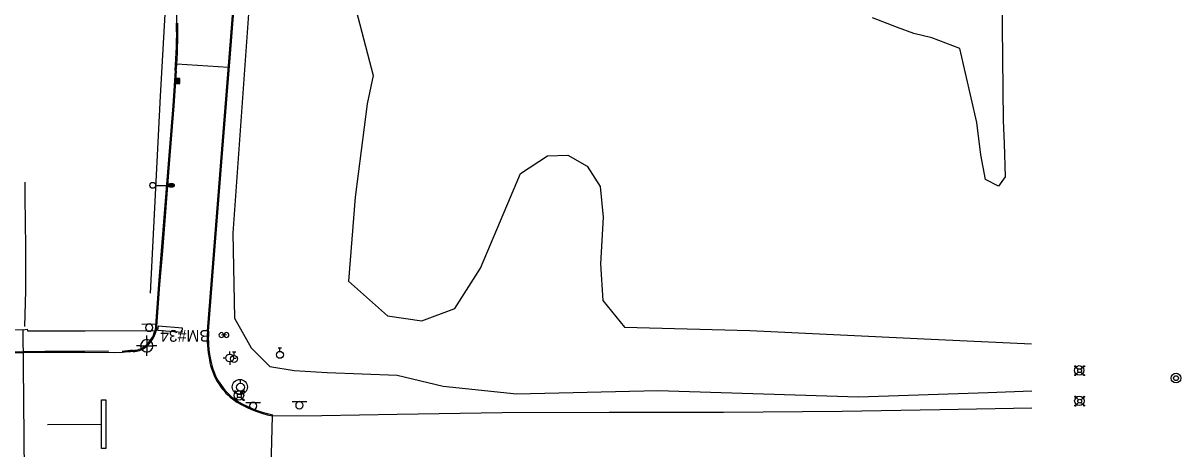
# Model space of a CAD drawing. Extents: x 2145380 to 2156929, y 139568 to 149130.
# Drawn here: x 2150933 to 2151525, y 140326 to 140544 of the extents above; entities that cross this region are included whole.
import ezdxf

# ---------------------------------------------------------------- set-up
doc = ezdxf.new("R2010")
doc.units = 0
for name, color, linetype in [('Default', 7, 'Continuous'), ('SURV_Benchmark', 7, 'Continuous'), ('SURV_Text', 7, 'Continuous'), ('TOPO_Asphalt', 7, 'Continuous'), ('TOPO_BRIDGE_Floor Deck', 7, 'Continuous'), ('TOPO_Curb Back', 7, 'Continuous'), ('TOPO_Fence', 7, 'Continuous'), ('TOPO_Flowline', 7, 'Continuous'), ('TOPO_Light Pole', 7, 'Continuous'), ('TOPO_Misc', 7, 'Continuous'), ('TOPO_Misc Line', 7, 'Continuous'), ('TOPO_Power Pole', 7, 'Continuous'), ('TOPO_San Manhole', 7, 'Continuous'), ('TOPO_Sidewalk', 7, 'Continuous'), ('TOPO_Sign', 7, 'Continuous'), ('TOPO_Tree', 7, 'Continuous'), ('TOPO_Wall Freestanding', 7, 'Continuous'), ('TOPO_Water Fire Hydrant', 7, 'Continuous'), ('TOPO_Water Valve', 7, 'Continuous')]:
    doc.layers.add(name, color=color, linetype=linetype)

# ---------------------------------------------------------------- blocks, each defined once
blk = doc.blocks.new('POST')
at = {"layer": 'TOPO_Misc'}
for start, end in [(90, 180), (180, 270), (360, 90), (270, 0)]:
    blk.add_arc((0, 0), 3.16, start, end, dxfattribs=at)
blk = doc.blocks.new('FIRHYD')
at = {"layer": 'TOPO_Water Fire Hydrant'}
for p, q in [((0, 10.2), (0, 17.3)), ((10.2, 0), (17.3, 0)), ((-10.2, 0), (-17.3, 0)), ((0, -10.2), (0, -17.3))]:
    blk.add_line(p, q, dxfattribs=at)
blk.add_circle((0, 0), 10.2, dxfattribs=at)
blk = doc.blocks.new('LP')
at = {"layer": 'TOPO_Light Pole'}
blk.add_line((3.8, 0), (20.3, 0), dxfattribs=at)
for points in [[(20.3, 0), (27.9, 0)], [(20.3, 0), (23.5, 0)], [(20.8, 1.3), (27.4, 1.3)], [(20.8, 1.3), (23.5, 1.3)], [(23.7, 1.3), (27.4, 1.3)], [(23.7, 0), (27.9, 0)], [(20.8, -1.3), (27.4, -1.3)], [(20.8, -1.3), (23.5, -1.3)], [(23.7, -1.3), (27.4, -1.3)]]:
    blk.add_lwpolyline(points, dxfattribs=at)
blk.add_circle((0, 0), 3.81, dxfattribs=at)
blk.add_ellipse((24.1, 0), major_axis=(3.81, 0), ratio=0.666667, dxfattribs=at)
blk = doc.blocks.new('CB')
at = {"layer": 'TOPO_Misc'}
for p, q in [((-3.1, 3), (3.2, 3)), ((-3.1, 2.7), (3.2, 2.7)), ((-3.1, 2.4), (3.2, 2.4)), ((-3.1, 2), (3.2, 2)), ((-3.1, 1.7), (3.2, 1.7)), ((-3.1, 1.4), (3.2, 1.4)), ((-3.1, 1.1), (3.2, 1.1)), ((-3.1, 0.8), (3.2, 0.8)), ((-3.1, 0.5), (3.2, 0.5)), ((-3.1, 0.1), (3.2, 0.1)), ((-3.1, -0.2), (3.2, -0.2)), ((-3.1, -0.5), (3.2, -0.5)), ((-3.1, -0.8), (3.2, -0.8)), ((-3.1, -1.1), (3.3, -1.1)), ((-3.1, -1.4), (3.3, -1.4)), ((-3.1, -1.8), (3.3, -1.8)), ((-3.1, -2.1), (3.3, -2.1)), ((-3.1, -2.4), (3.3, -2.4)), ((-3.1, -2.7), (3.3, -2.7)), ((-3.1, -3), (3.3, -3))]:
    blk.add_line(p, q, dxfattribs=at)
blk.add_lwpolyline([(3.3, -3.3), (3.2, 3.1), (-3.1, 3), (-3.1, -3.3), (3.3, -3.3)], dxfattribs=at)
blk = doc.blocks.new('POWPOL')
at = {"layer": 'TOPO_Power Pole'}
for p, q in [((0, 10.2), (0, 17.3)), ((0, -10.2), (0, -17.3))]:
    blk.add_line(p, q, dxfattribs=at)
blk.add_circle((0, 0), 10.2, dxfattribs=at)
blk = doc.blocks.new('HIGHMAST')
at = {"layer": 'Default'}
for p, q in [((-6.4, 5.7), (-6.2, 6.2)), ((-6.2, 5.2), (-6.4, 5.7)), ((-6.3, 5.9), (-5.9, 6.3)), ((-6.2, 5.3), (-6.3, 5.9)), ((-6.3, 5.7), (-5.2, 5.6)), ((-5.6, 5.1), (-6.3, 5.7)), ((-6.2, 6.2), (-5.7, 6.4)), ((-6.2, 5.8), (-5.9, 6.2)), ((-6.1, 5.4), (-6.2, 5.8)), ((-6.2, 5.3), (-6.2, 5.3)), ((-5.7, 5.1), (-6.2, 5.3)), ((-6.2, 5.2), (-6.2, 5.2)), ((-5.7, 5), (-6.2, 5.2)), ((-6.1, 5.7), (-5.8, 6)), ((-5.7, 5.4), (-6.1, 5.7)), ((-6.1, 5.4), (-6.1, 5.4)), ((-5.6, 5.2), (-6.1, 5.4)), ((-6, 5.9), (-5.5, 6)), ((-6, 5.5), (-6, 5.9)), ((-6, 5.5), (-6, 5.5)), ((-5.5, 5.4), (-6, 5.5)), ((-5.9, 6.3), (-5.3, 6.1)), ((-5.9, 6.2), (-5.4, 6.1)), ((-5.8, 5.8), (-5.9, 5.7)), ((-5.9, 5.7), (-5.8, 5.5)), ((-5.8, 6.3), (-5.6, 5.1)), ((-5.8, 5.8), (-5.8, 6.3)), ((-5.8, 6), (-5.8, 5.8)), ((-5.8, 6), (-5.4, 5.6)), ((-5.6, 5.6), (-5.8, 5.8)), ((-5.8, 5.5), (-5.6, 5.6)), ((-5.7, 6.4), (-5.2, 6.2)), ((-5.4, 5.6), (-5.7, 5.4)), ((-5.3, 5.3), (-5.7, 5.1)), ((-5.2, 5.2), (-5.7, 5)), ((-5.3, 5.6), (-5.6, 5.2)), ((-5.5, 6), (-5.5, 6)), ((-5.5, 6), (-5.5, 5.4)), ((-5.4, 6.1), (-5.4, 6)), ((-5.4, 6), (-5.3, 5.6)), ((-5.3, 6.1), (-5.3, 6.1)), ((-5.3, 6.1), (-5.1, 5.7)), ((-5.1, 5.7), (-5.3, 5.3)), ((-5.2, 6.2), (-5, 5.7)), ((-5.2, 6.2), (-5.2, 6.2)), ((-5, 5.7), (-5.2, 5.2)), ((-5.2, 5.2), (-1.8, 1.8)), ((5.2, 5.2), (1.8, 1.8)), ((5, 5.7), (5.2, 6.2)), ((5.2, 5.2), (5, 5.7)), ((5.1, 5.6), (5.7, 6.3)), ((5.1, 5.7), (5.3, 6.2)), ((6.3, 5.8), (5.1, 5.6)), ((5.3, 5.3), (5.1, 5.7)), ((5.2, 6.2), (5.7, 6.4)), ((5.2, 6.2), (5.2, 6.2)), ((5.2, 5.6), (5.4, 6.1)), ((5.6, 5.3), (5.2, 5.6)), ((5.7, 5), (5.2, 5.2)), ((5.3, 6.2), (5.9, 6.3)), ((5.3, 6.2), (5.3, 6.2)), ((5.7, 5.1), (5.3, 5.3)), ((5.4, 6.1), (5.8, 6.2)), ((5.4, 5.7), (5.7, 6.1)), ((5.4, 6.1), (5.4, 6.1)), ((5.4, 5.5), (5.5, 6)), ((5.6, 5.4), (5.4, 5.7)), ((6, 5.5), (5.4, 5.5)), ((5.5, 6), (5.9, 6)), ((5.5, 6), (5.5, 6)), ((5.7, 5.9), (5.5, 5.8)), ((5.5, 5.8), (5.6, 5.6)), ((5.7, 6.3), (5.6, 5.2)), ((5.6, 5.6), (5.8, 5.8)), ((6, 5.8), (5.6, 5.4)), ((6, 5.4), (5.6, 5.3)), ((5.7, 6.4), (6.2, 6.2)), ((5.7, 6.1), (6, 5.8)), ((5.8, 5.8), (5.7, 5.9)), ((6.1, 5.3), (5.7, 5.1)), ((6.2, 5.2), (5.7, 5)), ((5.8, 6.2), (6.2, 5.9)), ((5.8, 5.8), (6.3, 5.8)), ((6, 5.8), (5.8, 5.8)), ((5.9, 6.3), (6.3, 5.9)), ((5.9, 6), (6, 5.5)), ((6, 5.5), (6, 5.5)), ((6.1, 5.4), (6, 5.4)), ((6.2, 5.9), (6.1, 5.4)), ((6.3, 5.9), (6.1, 5.3)), ((6.1, 5.3), (6.1, 5.3)), ((6.2, 6.2), (6.4, 5.7)), ((6.4, 5.7), (6.2, 5.2)), ((6.2, 5.2), (6.2, 5.2)), ((-6.4, -5.7), (-6.2, -5.2)), ((-6.2, -6.2), (-6.4, -5.7)), ((-6.3, -5.9), (-6.1, -5.3)), ((-6.3, -5.8), (-5.1, -5.6)), ((-5.8, -5.8), (-6.3, -5.8)), ((-5.9, -6.3), (-6.3, -5.9)), ((-6.2, -5.2), (-5.7, -5)), ((-6.2, -5.2), (-6.2, -5.2)), ((-6.2, -5.9), (-6.1, -5.4)), ((-5.8, -6.2), (-6.2, -5.9)), ((-5.7, -6.4), (-6.2, -6.2)), ((-6.1, -5.3), (-5.7, -5.1)), ((-6.1, -5.3), (-6.1, -5.3)), ((-6.1, -5.4), (-6, -5.4)), ((-6, -5.4), (-5.6, -5.3)), ((-6, -5.8), (-5.6, -5.4)), ((-6, -5.5), (-6, -5.5)), ((-5.9, -6), (-6, -5.5)), ((-6, -5.5), (-5.4, -5.5)), ((-6, -5.8), (-5.8, -5.8)), ((-5.7, -6.1), (-6, -5.8)), ((-5.5, -6), (-5.9, -6)), ((-5.3, -6.2), (-5.9, -6.3)), ((-5.6, -5.6), (-5.8, -5.8)), ((-5.8, -5.8), (-5.7, -5.9)), ((-5.4, -6.1), (-5.8, -6.2)), ((-5.7, -5), (-5.2, -5.2)), ((-5.7, -5.1), (-5.3, -5.3)), ((-5.7, -6.3), (-5.6, -5.2)), ((-5.1, -5.6), (-5.7, -6.3)), ((-5.4, -5.7), (-5.7, -6.1)), ((-5.7, -5.9), (-5.5, -5.8)), ((-5.2, -6.2), (-5.7, -6.4)), ((-5.6, -5.3), (-5.2, -5.6)), ((-5.6, -5.4), (-5.4, -5.7)), ((-5.5, -5.8), (-5.6, -5.6)), ((-5.4, -5.5), (-5.5, -6)), ((-5.5, -6), (-5.5, -6)), ((-5.2, -5.6), (-5.4, -6.1)), ((-5.4, -6.1), (-5.4, -6.1)), ((-5.3, -5.3), (-5.1, -5.7)), ((-5.1, -5.7), (-5.3, -6.2)), ((-5.3, -6.2), (-5.3, -6.2)), ((-5.2, -5.2), (-1.8, -1.8)), ((-5.2, -5.2), (-5, -5.7)), ((-5, -5.7), (-5.2, -6.2)), ((-5.2, -6.2), (-5.2, -6.2)), ((5.2, -5.2), (1.8, -1.8)), ((5, -5.7), (5.2, -5.2)), ((5.2, -6.2), (5, -5.7)), ((5.1, -5.7), (5.3, -5.3)), ((5.3, -6.1), (5.1, -5.7)), ((5.2, -5.2), (5.7, -5)), ((6.3, -5.7), (5.2, -5.6)), ((5.7, -6.4), (5.2, -6.2)), ((5.2, -6.2), (5.2, -6.2)), ((5.3, -5.3), (5.7, -5.1)), ((5.3, -5.6), (5.6, -5.2)), ((5.4, -6), (5.3, -5.6)), ((5.3, -6.1), (5.3, -6.1)), ((5.9, -6.3), (5.3, -6.1)), ((5.4, -5.6), (5.7, -5.4)), ((5.8, -6), (5.4, -5.6)), ((5.4, -6.1), (5.4, -6)), ((5.9, -6.2), (5.4, -6.1)), ((5.5, -5.4), (6, -5.5)), ((5.5, -6), (5.5, -5.4)), ((6, -5.9), (5.5, -6)), ((5.5, -6), (5.5, -6)), ((5.6, -5.1), (6.3, -5.7)), ((5.8, -6.3), (5.6, -5.1)), ((5.6, -5.2), (6.1, -5.4)), ((5.8, -5.5), (5.6, -5.6)), ((5.6, -5.6), (5.8, -5.8)), ((5.7, -5), (6.2, -5.2)), ((5.7, -5.1), (6.2, -5.3)), ((5.7, -5.4), (6.1, -5.7)), ((6.2, -6.2), (5.7, -6.4)), ((5.9, -5.7), (5.8, -5.5)), ((5.8, -5.8), (5.9, -5.7)), ((6.1, -5.7), (5.8, -6)), ((5.8, -5.8), (5.8, -6.3)), ((5.8, -6), (5.8, -5.8)), ((6.2, -5.8), (5.9, -6.2)), ((6.3, -5.9), (5.9, -6.3)), ((6, -5.5), (6, -5.9)), ((6, -5.5), (6, -5.5)), ((6.1, -5.4), (6.2, -5.8)), ((6.1, -5.4), (6.1, -5.4)), ((6.2, -5.2), (6.2, -5.2)), ((6.2, -5.2), (6.4, -5.7)), ((6.2, -5.3), (6.3, -5.9)), ((6.2, -5.3), (6.2, -5.3)), ((6.4, -5.7), (6.2, -6.2))]:
    blk.add_line(p, q, dxfattribs=at)
for centre, radius in [((-0.5, 0.4), 6.15), ((0, 0), 2.5), ((0, 0), 2.5), ((0, 0), 2.5), ((0, 0), 2.5)]:
    blk.add_circle(centre, radius, dxfattribs=at)
blk = doc.blocks.new('WATVAL')
at = {"layer": 'Default'}
for p, q in [((-2.2, 9), (2.2, 9)), ((0, 4.5), (0, 9))]:
    blk.add_line(p, q, dxfattribs=at)
blk.add_circle((0, 0), 4.5, dxfattribs=at)
blk = doc.blocks.new('EXMHSS')
at = {"layer": 'Default'}
for radius in [6.3, 3.13]:
    blk.add_circle((0, 0), radius, dxfattribs=at)
blk = doc.blocks.new('BM')
at = {"layer": 'SURV_Benchmark'}
for p, q in [((-2.49, 0), (-4.16, 0)), ((0, 2.49), (0, 4.15)), ((4.16, 0), (2.49, 0)), ((0, -4.16), (0, -2.49))]:
    blk.add_line(p, q, dxfattribs=at)
for points in [[(-2.5, 0), (-2.49, 0), (0, 0), (0, -2.49), (0, -2.49)], [(-2.5, 0), (-2.49, 0), (0, 0), (0, -2.49), (0, -2.49)], [(0, 2.49), (0, 2.49), (0, 0), (2.49, 0), (2.49, 0), (2.49, 0)], [(0, 2.49), (0, 2.49), (0, 0), (2.49, 0), (2.49, 0), (2.49, 0), (2.49, 0)]]:
    blk.add_lwpolyline(points, dxfattribs=at)
for start, end in [(90.0638, 180.0068), (0.0638, 90.0068), (0.0638, 90.0068), (180.0638, 270.0068), (180.0638, 270.0068), (269.9472, 359.9927)]:
    blk.add_arc((0, 0), 2.5, start, end, dxfattribs=at)

msp = doc.modelspace()

# ---------------------------------------------------------------- linework, layer by layer
at = {"layer": 'TOPO_Asphalt'}
for p, q in [((2151011.36, 140522.97), (2151037.75, 140521.3)), ((2151060.21, 140342.83), (2151059.4, 140316.72))]:
    msp.add_line(p, q, dxfattribs=at)
for points in [[(2150983.56, 140375.19), (2150979.3, 140375.09), (2150976.4, 140375.25)], [(2151060.35, 140342.81), (2151085.48, 140343.02), (2151124.03, 140343.6), (2151177.83, 140344.58), (2151232.54, 140344.63), (2151291.1, 140344.74), (2151351.87, 140345.23), (2151401.83, 140345.98), (2151448.94, 140346.84)]]:
    msp.add_lwpolyline(points, dxfattribs=at)
at = {"layer": 'TOPO_BRIDGE_Floor Deck'}
msp.add_lwpolyline([(2150762.77, 140312.54), (2150933.49, 140313.77), (2150932.8, 140386.92), (2150762.17, 140384.76)], close=True, dxfattribs=at)
at = {"layer": 'TOPO_Curb Back'}
for points in [[(2151027.02, 140386.12), (2151029.79, 140420.98), (2151034.38, 140479.32), (2151038.82, 140534.66), (2151043.39, 140594.14), (2151047.14, 140643.46), (2151051.77, 140704.61), (2151055.46, 140753.14), (2151057.54, 140778.15)], [(2151027.62, 140386.07), (2151030.38, 140420.93), (2151034.98, 140479.27), (2151039.42, 140534.61), (2151043.99, 140594.09), (2151047.74, 140643.41), (2151052.37, 140704.57), (2151056.06, 140753.09), (2151058.14, 140778.1)], [(2151012.37, 140600.86), (2151011.56, 140563.07), (2151011.23, 140543.78)], [(2151010.5, 140519.48), (2151009.28, 140501.49), (2151006.92, 140471.76), (2151003.42, 140427.3), (2151001.94, 140410.12), (2151000.21, 140386.42)], [(2151011.1, 140519.43), (2151009.88, 140501.45), (2151007.51, 140471.71), (2151004.02, 140427.26), (2151002.53, 140410.08), (2151000.8, 140386.32)], [(2150976.39, 140375.85), (2150964.33, 140375.72), (2150943.86, 140375.76), (2150932.9, 140375.65), (2150899.52, 140375.1), (2150856.89, 140374.87), (2150804.09, 140374.43), (2150767.06, 140374.09), (2150736.46, 140373.91), (2150723.9, 140373.62)], [(2150976.4, 140375.25), (2150964.33, 140375.12), (2150943.87, 140375.16), (2150932.91, 140375.05), (2150899.53, 140374.5), (2150856.89, 140374.27), (2150804.09, 140373.83), (2150767.07, 140373.49), (2150736.47, 140373.31), (2150723.96, 140373.02)]]:
    msp.add_lwpolyline(points, dxfattribs=at)
for centre, radius, start, end in [((2150766.69, 140538.9), 244.59, 355.44479, 1.14398), ((2150766.7, 140538.9), 245.18, 355.44555, 1.14152), ((2150985.12, 140390.56), 15.65, 308.78266, 344.67121), ((2150985.12, 140390.56), 16.25, 308.7278, 344.88013), ((2151077.83, 140382.19), 50.96, 175.57175, 192.12198), ((2151077.83, 140382.19), 50.36, 175.57246, 192.1366), ((2150989.66, 140339.23), 37.08, 91.04518, 99.62904), ((2150989.66, 140339.22), 36.48, 91.03386, 99.62896), ((2150988.51, 140387.24), 10.95, 272.47648, 305.7985), ((2150988.51, 140387.24), 11.55, 272.43895, 305.87631), ((2151060.22, 140376.94), 32.67, 189.6133, 231.31306), ((2151060.22, 140376.94), 32.07, 189.58997, 231.27662), ((2151070.28, 140395.25), 53.37, 235.16948, 259.27092), ((2151070.28, 140395.25), 52.77, 235.19129, 259.27137)]:
    msp.add_arc(centre, radius, start, end, dxfattribs=at)
at = {"layer": 'TOPO_Fence'}
msp.add_lwpolyline([(2151018.46, 140773.41), (2151011.96, 140677.79), (2151007.46, 140587.59), (2151002.79, 140506.45), (2150997.74, 140405.63)], dxfattribs=at)
at = {"layer": 'TOPO_Flowline'}
msp.add_lwpolyline([(2150933.66, 140388.6), (2150934.15, 140406.79), (2150934.04, 140429.26), (2150933.74, 140454.54), (2150933.77, 140462.47)], dxfattribs=at)
at = {"layer": 'TOPO_Misc Line'}
msp.add_line((2150972.84, 140338.4), (2150945.11, 140338.26), dxfattribs=at)
for points in [[(2151014.26, 140387.63), (2151001.73, 140388.75), (2151001.55, 140386.7), (2151014.08, 140385.58)], [(2150975.1, 140350.96), (2150975.08, 140326.04), (2150972.83, 140326.05), (2150972.85, 140350.96)]]:
    msp.add_lwpolyline(points, close=True, dxfattribs=at)
at = {"layer": 'TOPO_Sidewalk'}
msp.add_lwpolyline([(2150932.81, 140386.91), (2150934.83, 140387.15), (2150934.94, 140386.38), (2150964.51, 140386.29), (2151000.21, 140386.42)], dxfattribs=at)
at = {"layer": 'TOPO_Sign'}
for points in [[(2150993.46, 140389.82), (2151000.95, 140389.83)], [(2150995.34, 140387.96), (2150995.34, 140387.96)], [(2150997.21, 140389.82), (2150997.21, 140389.82)], [(2150997.21, 140386.09), (2150997.21, 140386.09)], [(2150999.08, 140387.96), (2150999.08, 140387.96)], [(2151036.79, 140384.21), (2151034.18, 140384.15)], [(2151070.31, 140350.09), (2151077.8, 140350.09)], [(2151074.06, 140350.09), (2151074.06, 140350.09)], [(2151046.68, 140349.73), (2151054.18, 140349.73)], [(2151048.57, 140347.86), (2151048.57, 140347.86)], [(2151050.43, 140349.73), (2151050.43, 140349.73)], [(2151050.43, 140345.99), (2151050.43, 140345.99)], [(2151052.3, 140347.86), (2151052.3, 140347.86)], [(2151072.19, 140348.22), (2151072.19, 140348.22)], [(2151074.06, 140346.35), (2151074.06, 140346.35)], [(2151075.92, 140348.22), (2151075.92, 140348.22)]]:
    msp.add_lwpolyline(points, dxfattribs=at)
for centre, start, end in [((2150997.21, 140387.96), 89.99996, 180.00004), ((2150997.21, 140387.96), 179.99996, 270.00004), ((2150997.21, 140387.96), 359.99996, 90.00004), ((2150997.21, 140387.96), 269.99996, 0.00004), ((2151074.06, 140348.22), 89.99996, 180.00004), ((2151074.06, 140348.22), 359.99996, 90.00004), ((2151050.43, 140347.86), 89.99996, 180.00004), ((2151050.43, 140347.86), 179.99996, 270.00004), ((2151050.43, 140347.86), 359.99996, 90.00004), ((2151050.43, 140347.86), 269.99996, 0.00004), ((2151074.06, 140348.22), 179.99996, 270.00004), ((2151074.06, 140348.22), 269.99996, 0.00004)]:
    msp.add_arc(centre, 1.87, start, end, dxfattribs=at)
at = {"layer": 'TOPO_Tree'}
for points in [[(2151100.2, 140561.6), (2151111.88, 140517.01), (2151108.77, 140502.57), (2151102.62, 140454.69), (2151099.22, 140411.8), (2151119.23, 140393.96), (2151136.8, 140391.46), (2151153.59, 140397.72), (2151166.79, 140418.41), (2151187.24, 140466.82), (2151201.01, 140475.85), (2151211.43, 140476.24), (2151221.26, 140470.58), (2151228.02, 140460.25), (2151229.55, 140444.47), (2151228.21, 140420.63), (2151229.29, 140401.87), (2151240.39, 140388.13), (2151304.51, 140386.5), (2151393.81, 140382.23), (2151448.63, 140379.59)], [(2151433.46, 140558.16), (2151434.15, 140493.95), (2151434.76, 140482.18), (2151435.19, 140465.18), (2151431.78, 140460.3), (2151425.08, 140463.69), (2151422.84, 140476.35), (2151420.76, 140492.99), (2151412.03, 140530.88), (2151397.77, 140536.19), (2151388.56, 140538.42), (2151380.12, 140541.62), (2151367.36, 140546.57)], [(2151048.16, 140550.89), (2151040.01, 140436.32), (2151040.92, 140392.83), (2151049.39, 140377.64), (2151059.03, 140368.1), (2151071.47, 140366.03), (2151088.27, 140365.01), (2151124.1, 140363.67), (2151147.58, 140357.94), (2151185.1, 140354.06), (2151257.45, 140355.85), (2151360.13, 140352.59), (2151426.51, 140354.79), (2151448.86, 140355.58)]]:
    msp.add_lwpolyline(points, dxfattribs=at)
at = {"layer": 'TOPO_Wall Freestanding'}
msp.add_circle((2151043.62, 140357.58), 3.86, dxfattribs=at)

# ---------------------------------------------------------------- block references
at = {"layer": 'SURV_Benchmark', "xscale": 1.25, "yscale": 1.25}
msp.add_blockref('BM', (2150995.95, 140378.68), dxfattribs=at)
at = {"layer": 'TOPO_Light Pole', "xscale": 0.39370000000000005, "yscale": 0.3937000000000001}
for name, p in [('LP', (2150999.06, 140460.77)), ('HIGHMAST', (2151473.31, 140365.92)), ('HIGHMAST', (2151043.34, 140353.12)), ('HIGHMAST', (2151473.39, 140350.33))]:
    msp.add_blockref(name, p, dxfattribs=at)
at = {"layer": 'TOPO_Misc', "xscale": 0.39370000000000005, "yscale": 0.3937000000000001}
for name, p in [('CB', (2151011.65, 140514.2)), ('POST', (2151034.18, 140384.15)), ('POST', (2151036.79, 140384.21))]:
    msp.add_blockref(name, p, dxfattribs=at)
at = {"layer": 'TOPO_Power Pole', "xscale": 0.19685000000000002, "yscale": 0.19685000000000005}
msp.add_blockref('POWPOL', (2151043.94, 140357.45), dxfattribs=at)
at = {"layer": 'TOPO_San Manhole', "xscale": 0.39370000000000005, "yscale": 0.3937000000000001}
msp.add_blockref('EXMHSS', (2151522.64, 140362.12), dxfattribs=at)
at = {"layer": 'TOPO_Water Fire Hydrant', "xscale": 0.19685000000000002, "yscale": 0.19685000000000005}
msp.add_blockref('FIRHYD', (2151038.4, 140372.41), dxfattribs=at)
at = {"layer": 'TOPO_Water Valve', "xscale": 0.39370000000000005, "yscale": 0.3937000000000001}
for p in [(2151040.65, 140371.96), (2151064.1, 140374.03)]:
    msp.add_blockref('WATVAL', p, dxfattribs=at)

# ---------------------------------------------------------------- texts
at = {"layer": 'SURV_Text'}
msp.add_text('BM#34', height=6, rotation=180, dxfattribs=at).set_placement((2151028.28, 140386.73))

doc.saveas('drawing.dxf')
